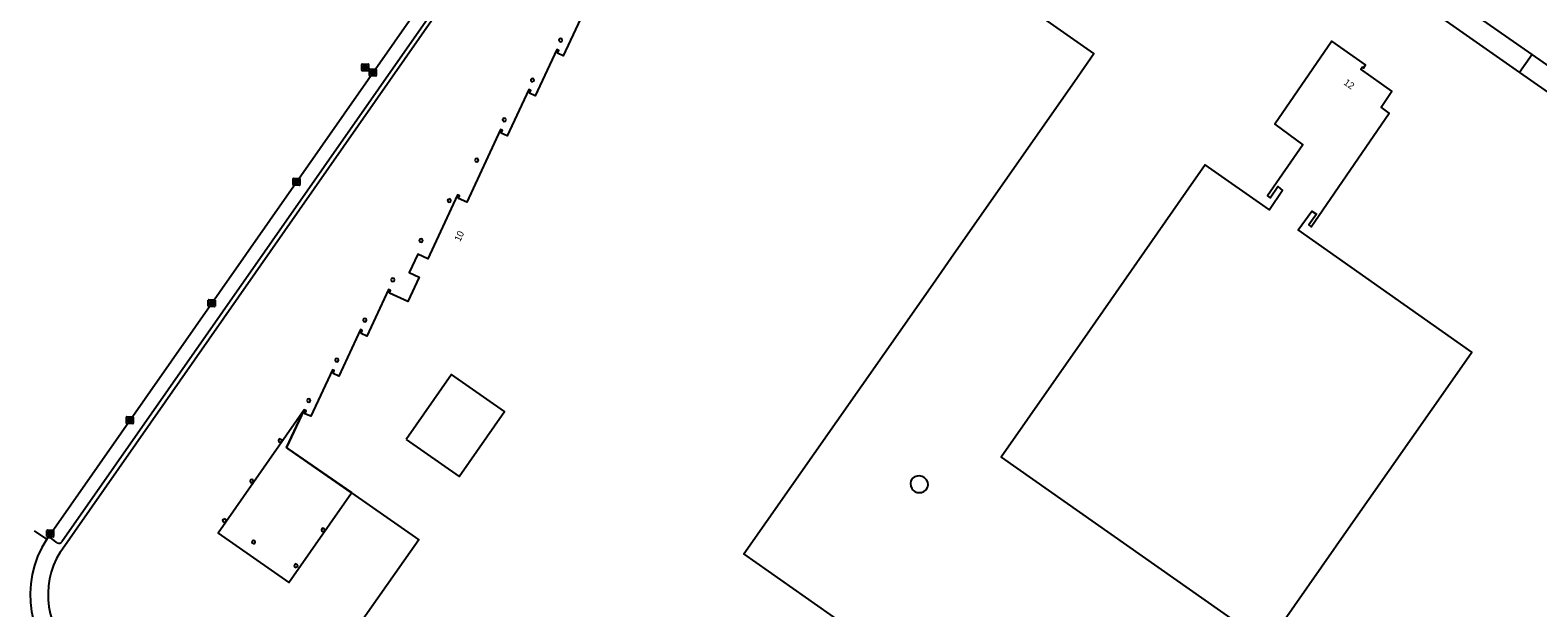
# Model space of a CAD drawing. Extents: x 155018 to 156648, y 383980 to 385733.
# Drawn here: x 155097.8 to 155319.7, y 385021.9 to 385106.9 of the extents above; entities that cross this region are included whole.
import ezdxf

# ---------------------------------------------------------------- set-up
doc = ezdxf.new("R2010")
doc.units = 0
for name, color, linetype in [('IMGEO_Kolk', 7, 'Continuous'), ('IMGEO_Opslagtank', 7, 'Continuous'), ('IMGEO_Pand', 7, 'Continuous'), ('IMGEO_Pand_nummerreeks', 7, 'Continuous'), ('IMGEO_Pand_overbouw', 7, 'Continuous'), ('IMGEO_Rijbaan_lokaal_gesloten', 7, 'Continuous'), ('IMGEO_Rijbaan_lokaal_open', 7, 'Continuous'), ('IMGEO_Rioolput', 7, 'Continuous'), ('IMGEO_Voetpad_open', 7, 'Continuous')]:
    doc.layers.add(name, color=color, linetype=linetype)

msp = doc.modelspace()

# ---------------------------------------------------------------- linework, layer by layer
at = {"layer": 'IMGEO_Kolk'}
for p, q in [((155147.75, 385100.28), (155147.75, 385101.14)), ((155147.83, 385101.21), (155148.68, 385101.21)), ((155148.68, 385100.21), (155147.83, 385100.21)), ((155148.24, 385100.99), (155148.26, 385100.99)), ((155148.26, 385100.43), (155148.24, 385100.43)), ((155148.75, 385101.14), (155148.75, 385100.28)), ((155136.5, 385084.19), (155136.5, 385085.04)), ((155136.58, 385085.11), (155137.43, 385085.11)), ((155137.43, 385084.11), (155136.58, 385084.11)), ((155136.99, 385084.89), (155137.02, 385084.89)), ((155137.01, 385084.33), (155136.99, 385084.33)), ((155137.51, 385085.04), (155137.51, 385084.19)), ((155124.02, 385066.31), (155124.02, 385067.17)), ((155124.09, 385067.24), (155124.95, 385067.24)), ((155124.95, 385066.24), (155124.09, 385066.24)), ((155124.53, 385066.46), (155124.5, 385066.46)), ((155124.51, 385067.02), (155124.53, 385067.02)), ((155125.02, 385067.17), (155125.02, 385066.31)), ((155111.99, 385049.09), (155111.99, 385049.95)), ((155112.06, 385050.02), (155112.91, 385050.02)), ((155112.91, 385049.02), (155112.06, 385049.02)), ((155112.47, 385049.8), (155112.5, 385049.8)), ((155112.5, 385049.24), (155112.47, 385049.24)), ((155112.99, 385049.95), (155112.99, 385049.09)), ((155100.27, 385032.4), (155100.27, 385033.25)), ((155100.35, 385033.33), (155101.2, 385033.33)), ((155100.76, 385033.11), (155100.79, 385033.11)), ((155101.27, 385033.25), (155101.27, 385032.4)), ((155101.2, 385032.33), (155100.35, 385032.33)), ((155100.78, 385032.55), (155100.76, 385032.55))]:
    msp.add_line(p, q, dxfattribs=at)
for points in [[(155147.75, 385100.28), (155147.75, 385101.14)], [(155147.83, 385101.21), (155148.68, 385101.21)], [(155148.68, 385100.21), (155147.83, 385100.21)], [(155148.07, 385100.91), (155148.2, 385100.91), (155148.2, 385100.76), (155148.32, 385100.91), (155148.49, 385100.91), (155148.34, 385100.76), (155148.5, 385100.51), (155148.34, 385100.51), (155148.26, 385100.67), (155148.2, 385100.61), (155148.2, 385100.51), (155148.07, 385100.51), (155148.07, 385100.91)], [(155148.75, 385101.14), (155148.75, 385100.28)], [(155136.5, 385084.19), (155136.5, 385085.04)], [(155136.58, 385085.11), (155137.43, 385085.11)], [(155137.43, 385084.11), (155136.58, 385084.11)], [(155136.82, 385084.81), (155136.95, 385084.81), (155136.95, 385084.66), (155137.08, 385084.81), (155137.24, 385084.81), (155137.1, 385084.66), (155137.25, 385084.41), (155137.1, 385084.41), (155137.01, 385084.58), (155136.95, 385084.51), (155136.95, 385084.41), (155136.82, 385084.41), (155136.82, 385084.81)], [(155137.51, 385085.04), (155137.51, 385084.19)], [(155124.02, 385066.31), (155124.02, 385067.17)], [(155124.09, 385067.24), (155124.95, 385067.24)], [(155124.95, 385066.24), (155124.09, 385066.24)], [(155124.34, 385066.94), (155124.46, 385066.94), (155124.46, 385066.79), (155124.59, 385066.94), (155124.76, 385066.94), (155124.61, 385066.79), (155124.76, 385066.54), (155124.61, 385066.54), (155124.53, 385066.7), (155124.46, 385066.64), (155124.46, 385066.54), (155124.34, 385066.54), (155124.34, 385066.94)], [(155125.02, 385067.17), (155125.02, 385066.31)], [(155111.99, 385049.09), (155111.99, 385049.95)], [(155112.06, 385050.02), (155112.91, 385050.02)], [(155112.91, 385049.02), (155112.06, 385049.02)], [(155112.31, 385049.72), (155112.43, 385049.72), (155112.43, 385049.57), (155112.56, 385049.72), (155112.72, 385049.72), (155112.58, 385049.57), (155112.73, 385049.32), (155112.58, 385049.32), (155112.49, 385049.48), (155112.43, 385049.42), (155112.43, 385049.32), (155112.31, 385049.32), (155112.31, 385049.72)], [(155112.99, 385049.95), (155112.99, 385049.09)], [(155100.27, 385032.4), (155100.27, 385033.25)], [(155100.35, 385033.33), (155101.2, 385033.33)], [(155100.59, 385033.03), (155100.72, 385033.03), (155100.72, 385032.88), (155100.85, 385033.03), (155101.01, 385033.03), (155100.86, 385032.88), (155101.02, 385032.63), (155100.86, 385032.63), (155100.78, 385032.79), (155100.72, 385032.72), (155100.72, 385032.63), (155100.59, 385032.63), (155100.59, 385033.03)], [(155101.27, 385033.25), (155101.27, 385032.4)], [(155101.2, 385032.33), (155100.35, 385032.33)]]:
    msp.add_lwpolyline(points, dxfattribs=at)
for centre, start, end in [((155147.83, 385101.13), 91.552, 178.448), ((155147.83, 385101.13), 91.552, 178.448), ((155147.83, 385100.29), 181.552, 268.448), ((155147.83, 385100.29), 181.552, 268.448), ((155148.68, 385101.13), 1.552, 88.448), ((155148.68, 385101.13), 1.552, 88.448), ((155148.68, 385100.29), 271.552, 358.448), ((155148.68, 385100.29), 271.552, 358.448), ((155136.58, 385085.04), 91.552, 178.448), ((155136.58, 385085.04), 91.552, 178.448), ((155136.58, 385084.19), 181.552, 268.448), ((155136.58, 385084.19), 181.552, 268.448), ((155137.43, 385085.04), 1.552, 88.448), ((155137.43, 385085.04), 1.552, 88.448), ((155137.43, 385084.19), 271.552, 358.448), ((155137.43, 385084.19), 271.552, 358.448), ((155124.09, 385067.16), 91.552, 178.448), ((155124.09, 385067.16), 91.552, 178.448), ((155124.09, 385066.32), 181.552, 268.448), ((155124.09, 385066.32), 181.552, 268.448), ((155124.94, 385067.16), 1.552, 88.448), ((155124.94, 385067.16), 1.552, 88.448), ((155124.94, 385066.32), 271.552, 358.448), ((155124.94, 385066.32), 271.552, 358.448), ((155112.06, 385049.94), 91.552, 178.448), ((155112.06, 385049.94), 91.552, 178.448), ((155112.06, 385049.09), 181.552, 268.448), ((155112.06, 385049.09), 181.552, 268.448), ((155112.91, 385049.94), 1.552, 88.448), ((155112.91, 385049.94), 1.552, 88.448), ((155112.91, 385049.09), 271.552, 358.448), ((155112.91, 385049.09), 271.552, 358.448), ((155100.35, 385033.25), 91.552, 178.448), ((155100.35, 385033.25), 91.552, 178.448), ((155101.2, 385033.25), 1.552, 88.448), ((155101.2, 385033.25), 1.552, 88.448), ((155100.35, 385032.4), 181.552, 268.448), ((155100.35, 385032.4), 181.552, 268.448), ((155101.2, 385032.4), 271.552, 358.448), ((155101.2, 385032.4), 271.552, 358.448)]:
    msp.add_arc(centre, 0.0765, start, end, dxfattribs=at)
for centre, major_axis, ratio, start_param, end_param in [((155148.24, 385100.71), (-0.387, 0.002), 0.722429, 4.712389, 7.853982), ((155148.26, 385100.71), (-0.39, 0.002), 0.717154, 1.570796, 4.712389), ((155136.99, 385084.61), (-0.387, 0.002), 0.722429, 4.712389, 7.853982), ((155137.02, 385084.61), (-0.39, 0.002), 0.717154, 1.570796, 4.712389), ((155124.51, 385066.74), (-0.387, 0.002), 0.722429, 4.712389, 7.853982), ((155124.53, 385066.74), (-0.39, 0.002), 0.717154, 1.570796, 4.712389), ((155112.47, 385049.52), (-0.387, 0.002), 0.722429, 4.712389, 7.853982), ((155112.5, 385049.52), (-0.39, 0.002), 0.717154, 1.570796, 4.712389), ((155100.76, 385032.83), (-0.387, 0.002), 0.722429, 4.712389, 7.853982), ((155100.78, 385032.83), (-0.39, 0.002), 0.717154, 1.570796, 4.712389)]:
    msp.add_ellipse(centre, major_axis=major_axis, ratio=ratio, start_param=start_param, end_param=end_param, dxfattribs=at)
at = {"layer": 'IMGEO_Opslagtank'}
for centre, radius, start, end in [((155228.69, 385040.14), 1.31, 142.9034, 353.3422), ((155228.6, 385039.91), 1.4, 3.2005, 133.0451)]:
    msp.add_arc(centre, radius, start, end, dxfattribs=at)
at = {"layer": 'IMGEO_Pand'}
for points in [[(155230.66, 385069.55), (155233.76, 385073.98), (155251.52, 385099.4), (155254.39, 385103.49), (155221.35, 385126.65)], [(155179.56, 385110.19), (155176.27, 385103.18), (155175.44, 385103.55), (155175.62, 385103.95), (155175.33, 385104.09), (155172.14, 385097.27), (155171.29, 385097.68), (155171.48, 385098.07), (155171.2, 385098.21), (155168, 385091.36), (155167.15, 385091.77), (155167.34, 385092.17), (155167.05, 385092.31), (155162.06, 385081.61), (155160.84, 385082.16), (155161.02, 385082.56), (155160.73, 385082.7), (155156.33, 385073.27), (155154.88, 385073.97), (155153.61, 385071.23), (155155.08, 385070.56), (155153.39, 385066.98), (155150.68, 385068.23), (155150.83, 385068.6), (155150.54, 385068.74), (155147.36, 385061.9), (155146.51, 385062.29), (155146.7, 385062.71), (155146.41, 385062.85), (155143.23, 385056.01), (155142.39, 385056.38), (155142.58, 385056.81), (155142.29, 385056.94), (155139.1, 385050.1), (155138.25, 385050.46), (155138.44, 385050.89), (155138.14, 385051.02), (155135.55, 385045.47), (155135.81, 385045.29), (155145.1, 385038.85), (155145.13, 385038.83), (155155.03, 385031.91), (155138.55, 385008.43)], [(155175.88, 385105.72), (155175.68, 385105.61)], [(155252.68, 385061.18), (155240.71, 385044.07), (155279.93, 385016.52), (155291.83, 385033.6), (155307.14, 385055.43), (155310.02, 385059.52), (155284.45, 385077.53), (155286.45, 385080.31), (155287.12, 385079.85), (155286, 385078.27), (155286.38, 385078), (155297.85, 385094.72), (155296.65, 385095.58), (155298.22, 385097.96), (155293.66, 385101.19), (155293.86, 385101.49), (155294.05, 385101.35), (155294.36, 385101.84), (155289.41, 385105.32), (155281.03, 385093.08), (155285.15, 385090.06), (155279.94, 385082.56), (155280.32, 385082.26), (155281.43, 385083.9), (155282.15, 385083.34), (155280.21, 385080.5), (155270.77, 385087.12), (155267.91, 385083.02), (155252.68, 385061.18)], [(155171.73, 385099.84), (155171.53, 385099.74)], [(155167.59, 385093.99), (155167.39, 385093.88)], [(155219.21, 385018.36), (155202.84, 385029.83), (155223.54, 385059.39), (155230.66, 385069.55)], [(155153.13, 385046.68), (155160.97, 385041.21), (155167.64, 385050.77), (155159.81, 385056.24), (155153.13, 385046.68)], [(155140.93, 385033.09), (155141.13, 385033.2)]]:
    msp.add_lwpolyline(points, dxfattribs=at)
for centre, start, end in [((155175.88, 385105.47), 144.9078, 270.1878), ((155175.88, 385105.47), 270, 90), ((155171.73, 385099.59), 145.0369, 269.9394), ((155171.73, 385099.59), 270, 90), ((155167.59, 385093.74), 144.9078, 270.1878), ((155167.59, 385093.74), 270, 90), ((155163.55, 385087.8), 90, 270), ((155163.55, 385087.8), 270, 90), ((155159.5, 385081.85), 90, 270), ((155159.5, 385081.85), 270, 90), ((155155.34, 385075.97), 90, 270), ((155155.34, 385075.97), 270, 90), ((155151.19, 385070.17), 90, 270), ((155151.19, 385070.17), 270, 90), ((155147.07, 385064.25), 90, 270), ((155147.07, 385064.25), 270, 90), ((155142.95, 385058.35), 90, 270), ((155142.95, 385058.35), 270, 90), ((155138.81, 385052.41), 90, 270), ((155138.81, 385052.41), 270, 90), ((155134.6, 385046.5), 90, 270), ((155134.6, 385046.5), 270, 90), ((155130.42, 385040.54), 90, 270), ((155130.42, 385040.54), 270, 90), ((155126.39, 385034.71), 90, 270), ((155126.39, 385034.71), 270, 90), ((155140.93, 385033.34), 90, 270), ((155140.93, 385033.34), 324.9078, 90.1878), ((155130.7, 385031.56), 90, 270), ((155130.7, 385031.56), 270, 90), ((155136.94, 385028.08), 90, 270), ((155136.94, 385028.08), 270, 90)]:
    msp.add_arc(centre, 0.25, start, end, dxfattribs=at)
at = {"layer": 'IMGEO_Pand_overbouw'}
msp.add_lwpolyline([(155135.81, 385045.29), (155135.55, 385045.47), (155138.14, 385051.02), (155125.46, 385032.85), (155135.88, 385025.58), (155145.13, 385038.83)], close=True, dxfattribs=at)
at = {"layer": 'IMGEO_Rijbaan_lokaal_gesloten'}
for points in [[(155100.24, 385031.99), (155154.95, 385110.29), (155160.52, 385118.21), (155164.16, 385123.4)], [(155318.91, 385103.34), (155293.87, 385120.84), (155293.03, 385121.5), (155291.11, 385122.81)], [(155326.85, 385097.79), (155318.91, 385103.34)], [(155100.24, 385031.99), (155098.46, 385033.23)]]:
    msp.add_lwpolyline(points, dxfattribs=at)
msp.add_arc((155112.68, 385023.84), 14.87, 146.7799, 232.6701, dxfattribs=at)
at = {"layer": 'IMGEO_Rijbaan_lokaal_open'}
for points in [[(155318.91, 385103.34), (155317.04, 385100.72)], [(155317.04, 385100.72), (155324.96, 385095.15)]]:
    msp.add_lwpolyline(points, dxfattribs=at)
at = {"layer": 'IMGEO_Rioolput'}
for p, q in [((155146.62, 385101.03), (155146.62, 385101.88)), ((155146.69, 385101.95), (155147.54, 385101.95)), ((155147.1, 385101.73), (155147.13, 385101.73)), ((155147.62, 385101.88), (155147.62, 385101.03)), ((155147.54, 385100.95), (155146.69, 385100.95)), ((155147.13, 385101.17), (155147.1, 385101.17))]:
    msp.add_line(p, q, dxfattribs=at)
for points in [[(155146.62, 385101.03), (155146.62, 385101.88)], [(155146.69, 385101.95), (155147.54, 385101.95)], [(155147.2, 385101.65), (155146.95, 385101.65), (155146.95, 385101.25)], [(155147.13, 385101.57), (155147.08, 385101.57), (155147.08, 385101.49)], [(155147.08, 385101.49), (155147.13, 385101.49)], [(155147.62, 385101.88), (155147.62, 385101.03)], [(155147.54, 385100.95), (155146.69, 385100.95)], [(155146.95, 385101.25), (155147.08, 385101.25), (155147.08, 385101.42), (155147.09, 385101.42)], [(155147.13, 385101.39), (155147.21, 385101.25), (155147.34, 385101.25), (155147.28, 385101.38)]]:
    msp.add_lwpolyline(points, dxfattribs=at)
for centre, radius, start, end in [((155146.69, 385101.88), 0.0765, 91.552, 178.448), ((155146.69, 385101.88), 0.0765, 91.552, 178.448), ((155147.14, 385101.48), 0.0964, 77.0061, 93.1865), ((155147.11, 385101.68), 0.19, 274.7715, 282.9687), ((155147.15, 385101.53), 0.0378, 276.6634, 79.6772), ((155147.2, 385101.54), 0.109, 350.3612, 89.416), ((155147.2, 385101.54), 0.112, 277.5842, 350.9817), ((155147.54, 385101.88), 0.0765, 1.552, 88.448), ((155147.54, 385101.88), 0.0765, 1.552, 88.448), ((155146.69, 385101.03), 0.0765, 181.552, 268.448), ((155146.69, 385101.03), 0.0765, 181.552, 268.448), ((155147.09, 385101.36), 0.0533, 26.0293, 88.6989), ((155147.19, 385101.33), 0.108, 29.5134, 73.7905), ((155147.54, 385101.03), 0.0765, 271.552, 358.448), ((155147.54, 385101.03), 0.0765, 271.552, 358.448)]:
    msp.add_arc(centre, radius, start, end, dxfattribs=at)
for centre, major_axis, ratio, start_param, end_param in [((155147.1, 385101.45), (-0.387, 0.002), 0.722429, 4.712389, 7.853982), ((155147.13, 385101.45), (-0.39, 0.002), 0.717154, 1.570796, 4.712389)]:
    msp.add_ellipse(centre, major_axis=major_axis, ratio=ratio, start_param=start_param, end_param=end_param, dxfattribs=at)
at = {"layer": 'IMGEO_Voetpad_open'}
for points in [[(155281.52, 385125.64), (155281.33, 385125.34), (155288.02, 385120.66), (155288.14, 385120.83), (155288.53, 385120.61), (155289.29, 385120.2), (155292, 385118.3), (155317.04, 385100.72)], [(155102.21, 385030.07), (155157.22, 385108.83), (155167.05, 385122.87), (155166.95, 385122.9)], [(155165.88, 385122.21), (155156.74, 385109.21), (155102.48, 385031.58)], [(155101.79, 385031.46), (155100.93, 385032.09)]]:
    msp.add_lwpolyline(points, dxfattribs=at)
for centre, radius, start, end in [((155100.64, 385031.7), 0.493, 53.5186, 143.8991), ((155102.08, 385031.87), 0.499, 234.852, 324.3139), ((155112.47, 385023.79), 12.03, 148.5642, 228.2134)]:
    msp.add_arc(centre, radius, start, end, dxfattribs=at)

# ---------------------------------------------------------------- texts
at = {"layer": 'IMGEO_Pand_nummerreeks'}
for s, rotation, p in [('12', 324.6686, (155291.06, 385099.02)), ('10', 64.962, (155161.1, 385075.73))]:
    msp.add_text(s, height=1, rotation=rotation, dxfattribs=at).set_placement(p)

doc.saveas('drawing.dxf')
